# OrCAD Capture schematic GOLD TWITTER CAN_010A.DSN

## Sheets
1 PAGE1_PROPRIETARY: title: PROPRIETARY; rev: A; note: GOLD TWITTER CAN
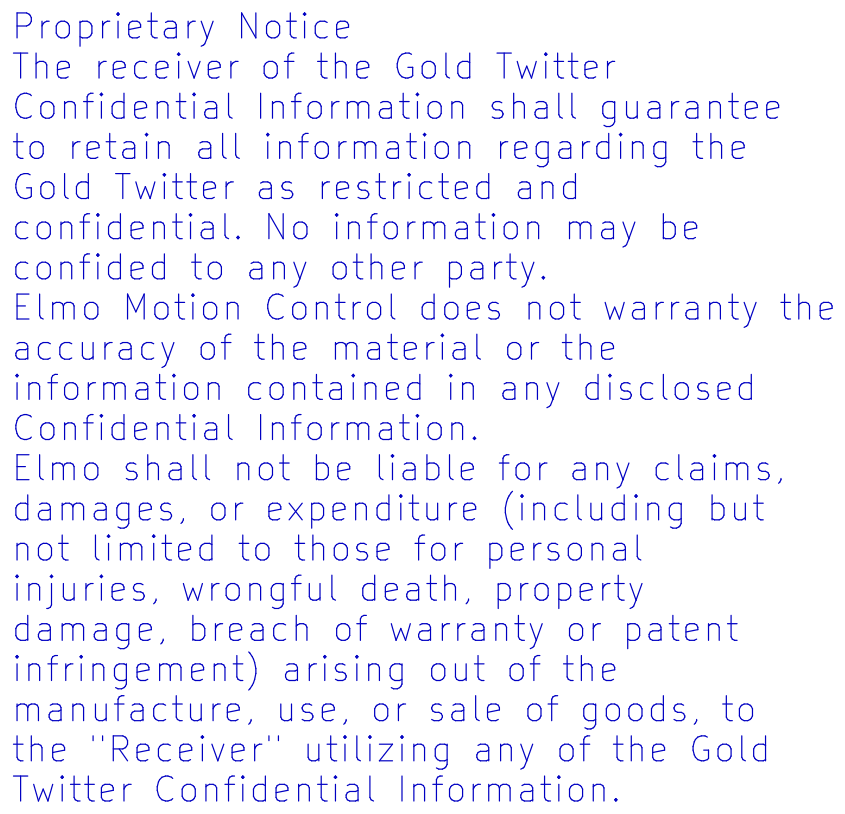
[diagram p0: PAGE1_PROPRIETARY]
2 PAGE2: size A4; title: TWI_E_B_Can_Connectors 01_200v; note: GOLD TWITTER CAN_010A.DSN
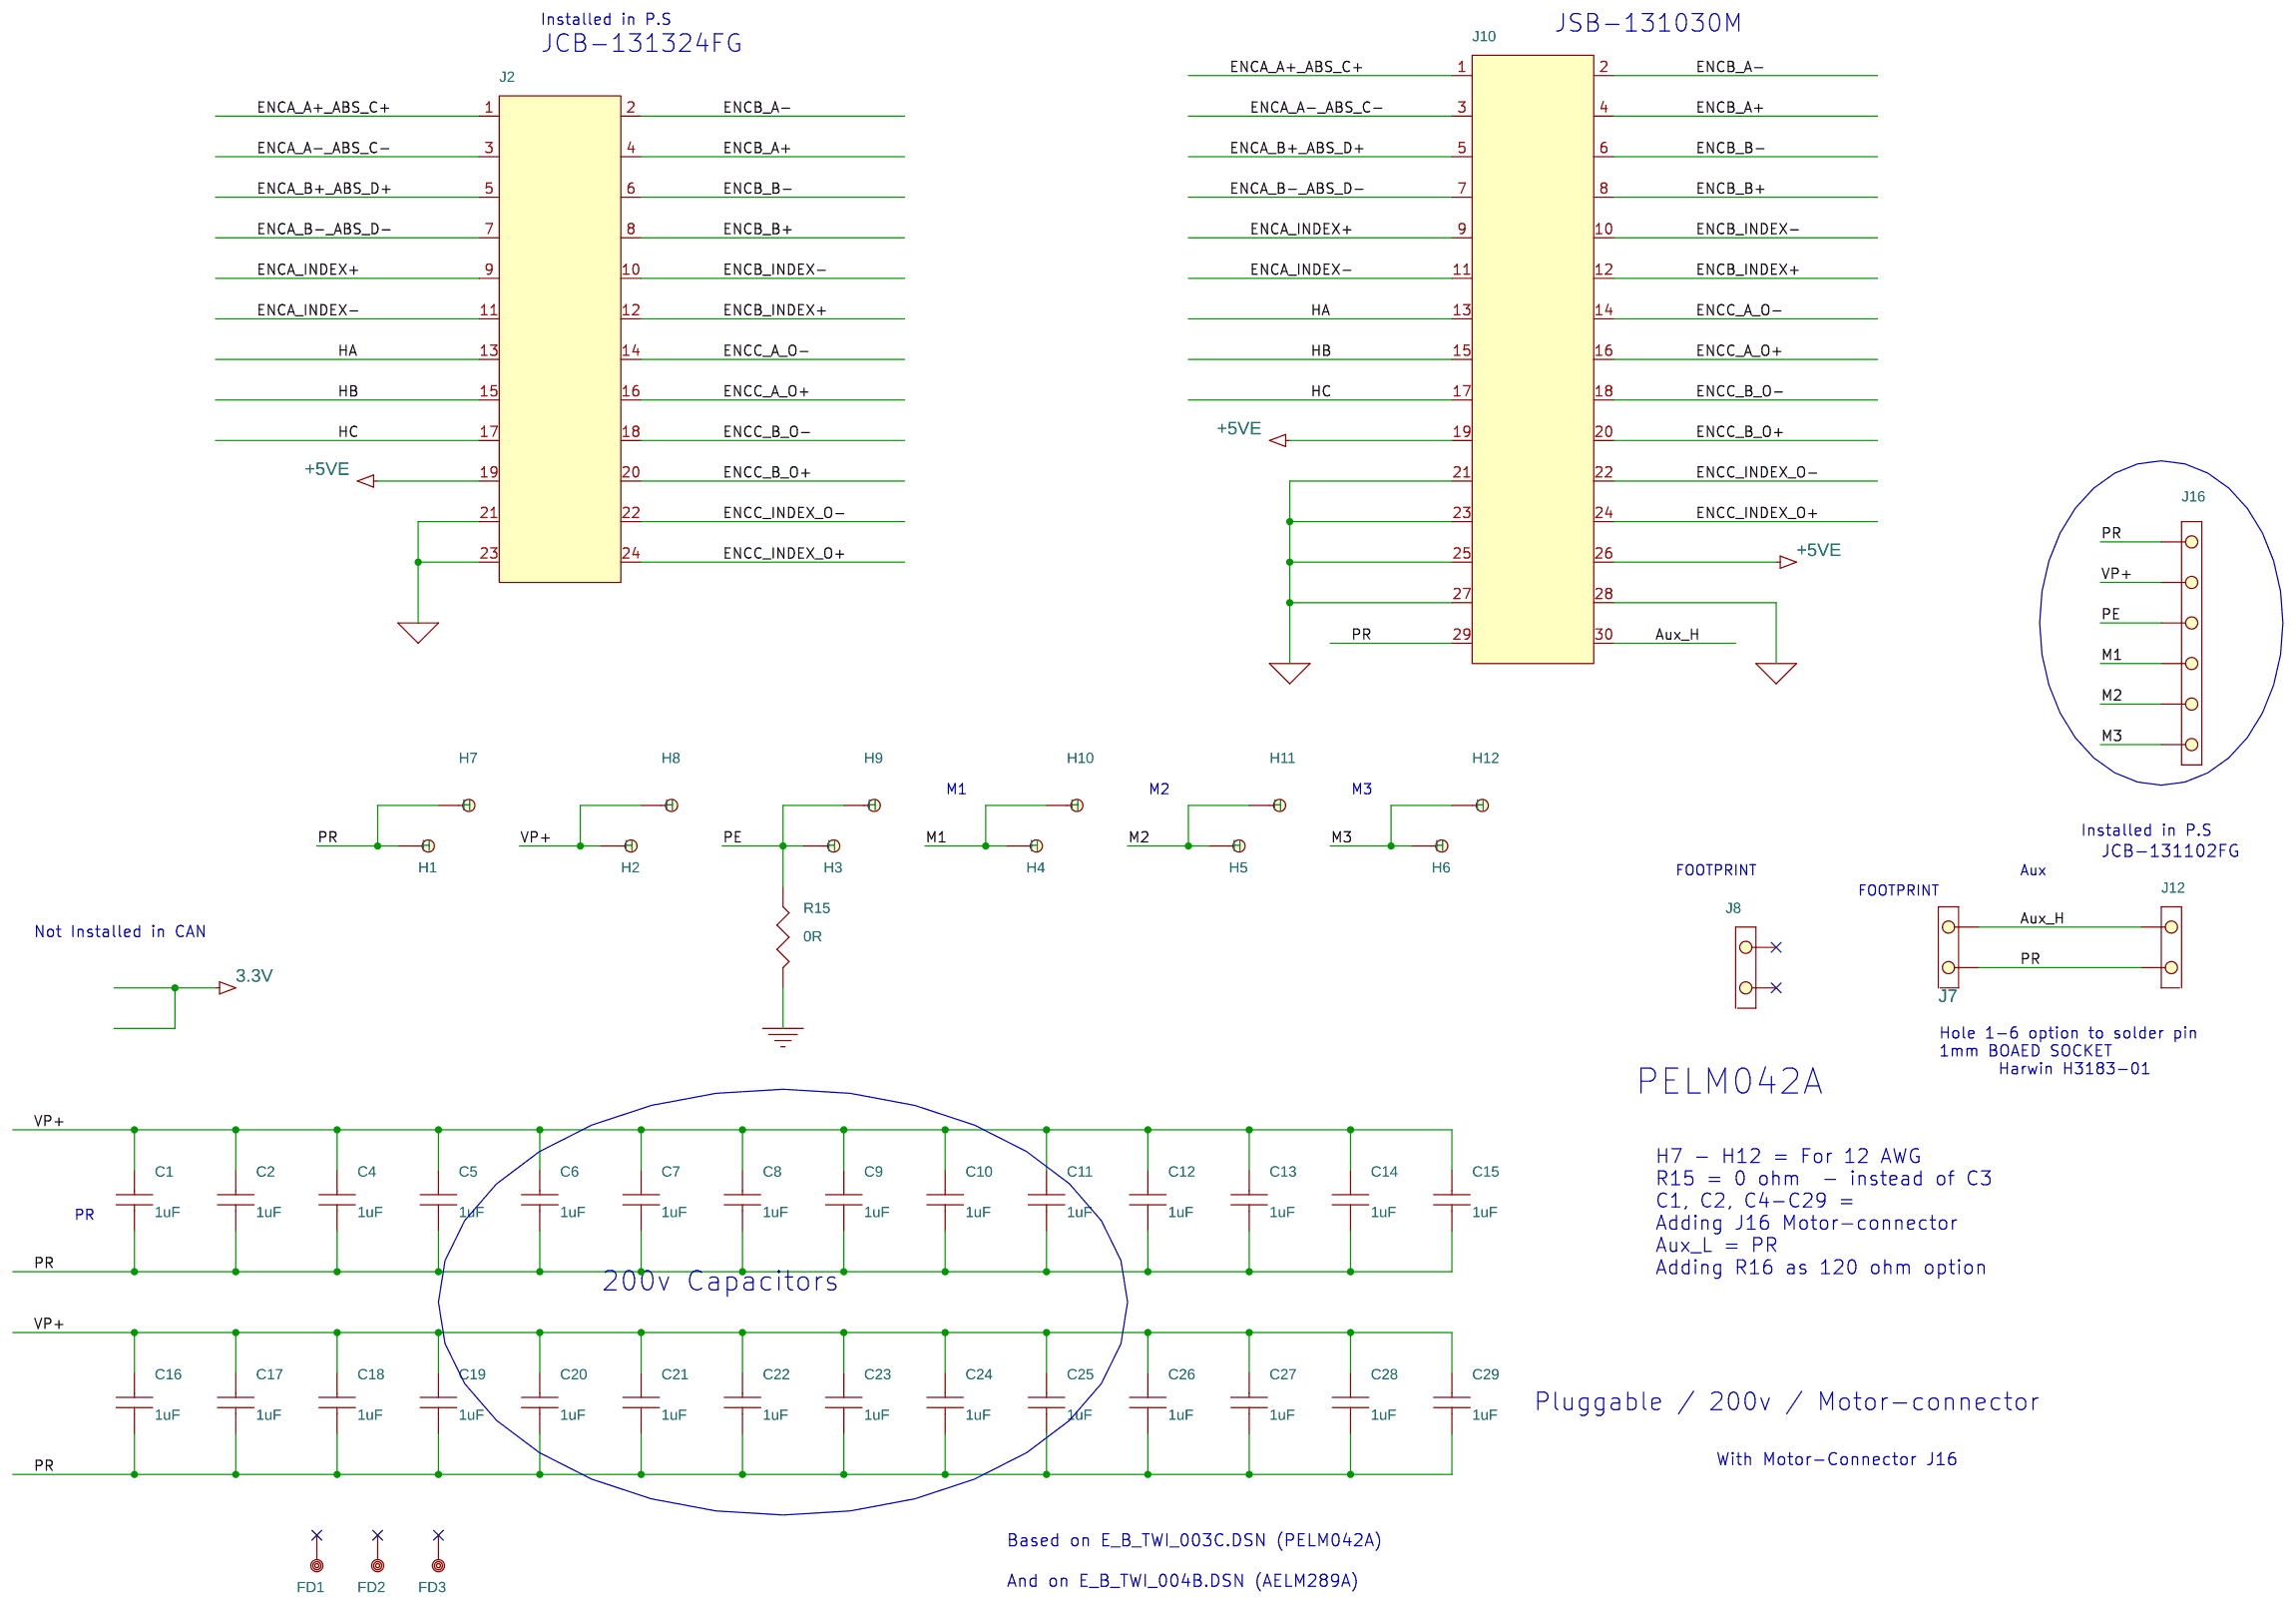
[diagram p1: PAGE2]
3 PAGE3: size A4; title: TWI_E_B_Can_Connectors 02_200v; note: GOLD TWITTER CAN_010A.DSN
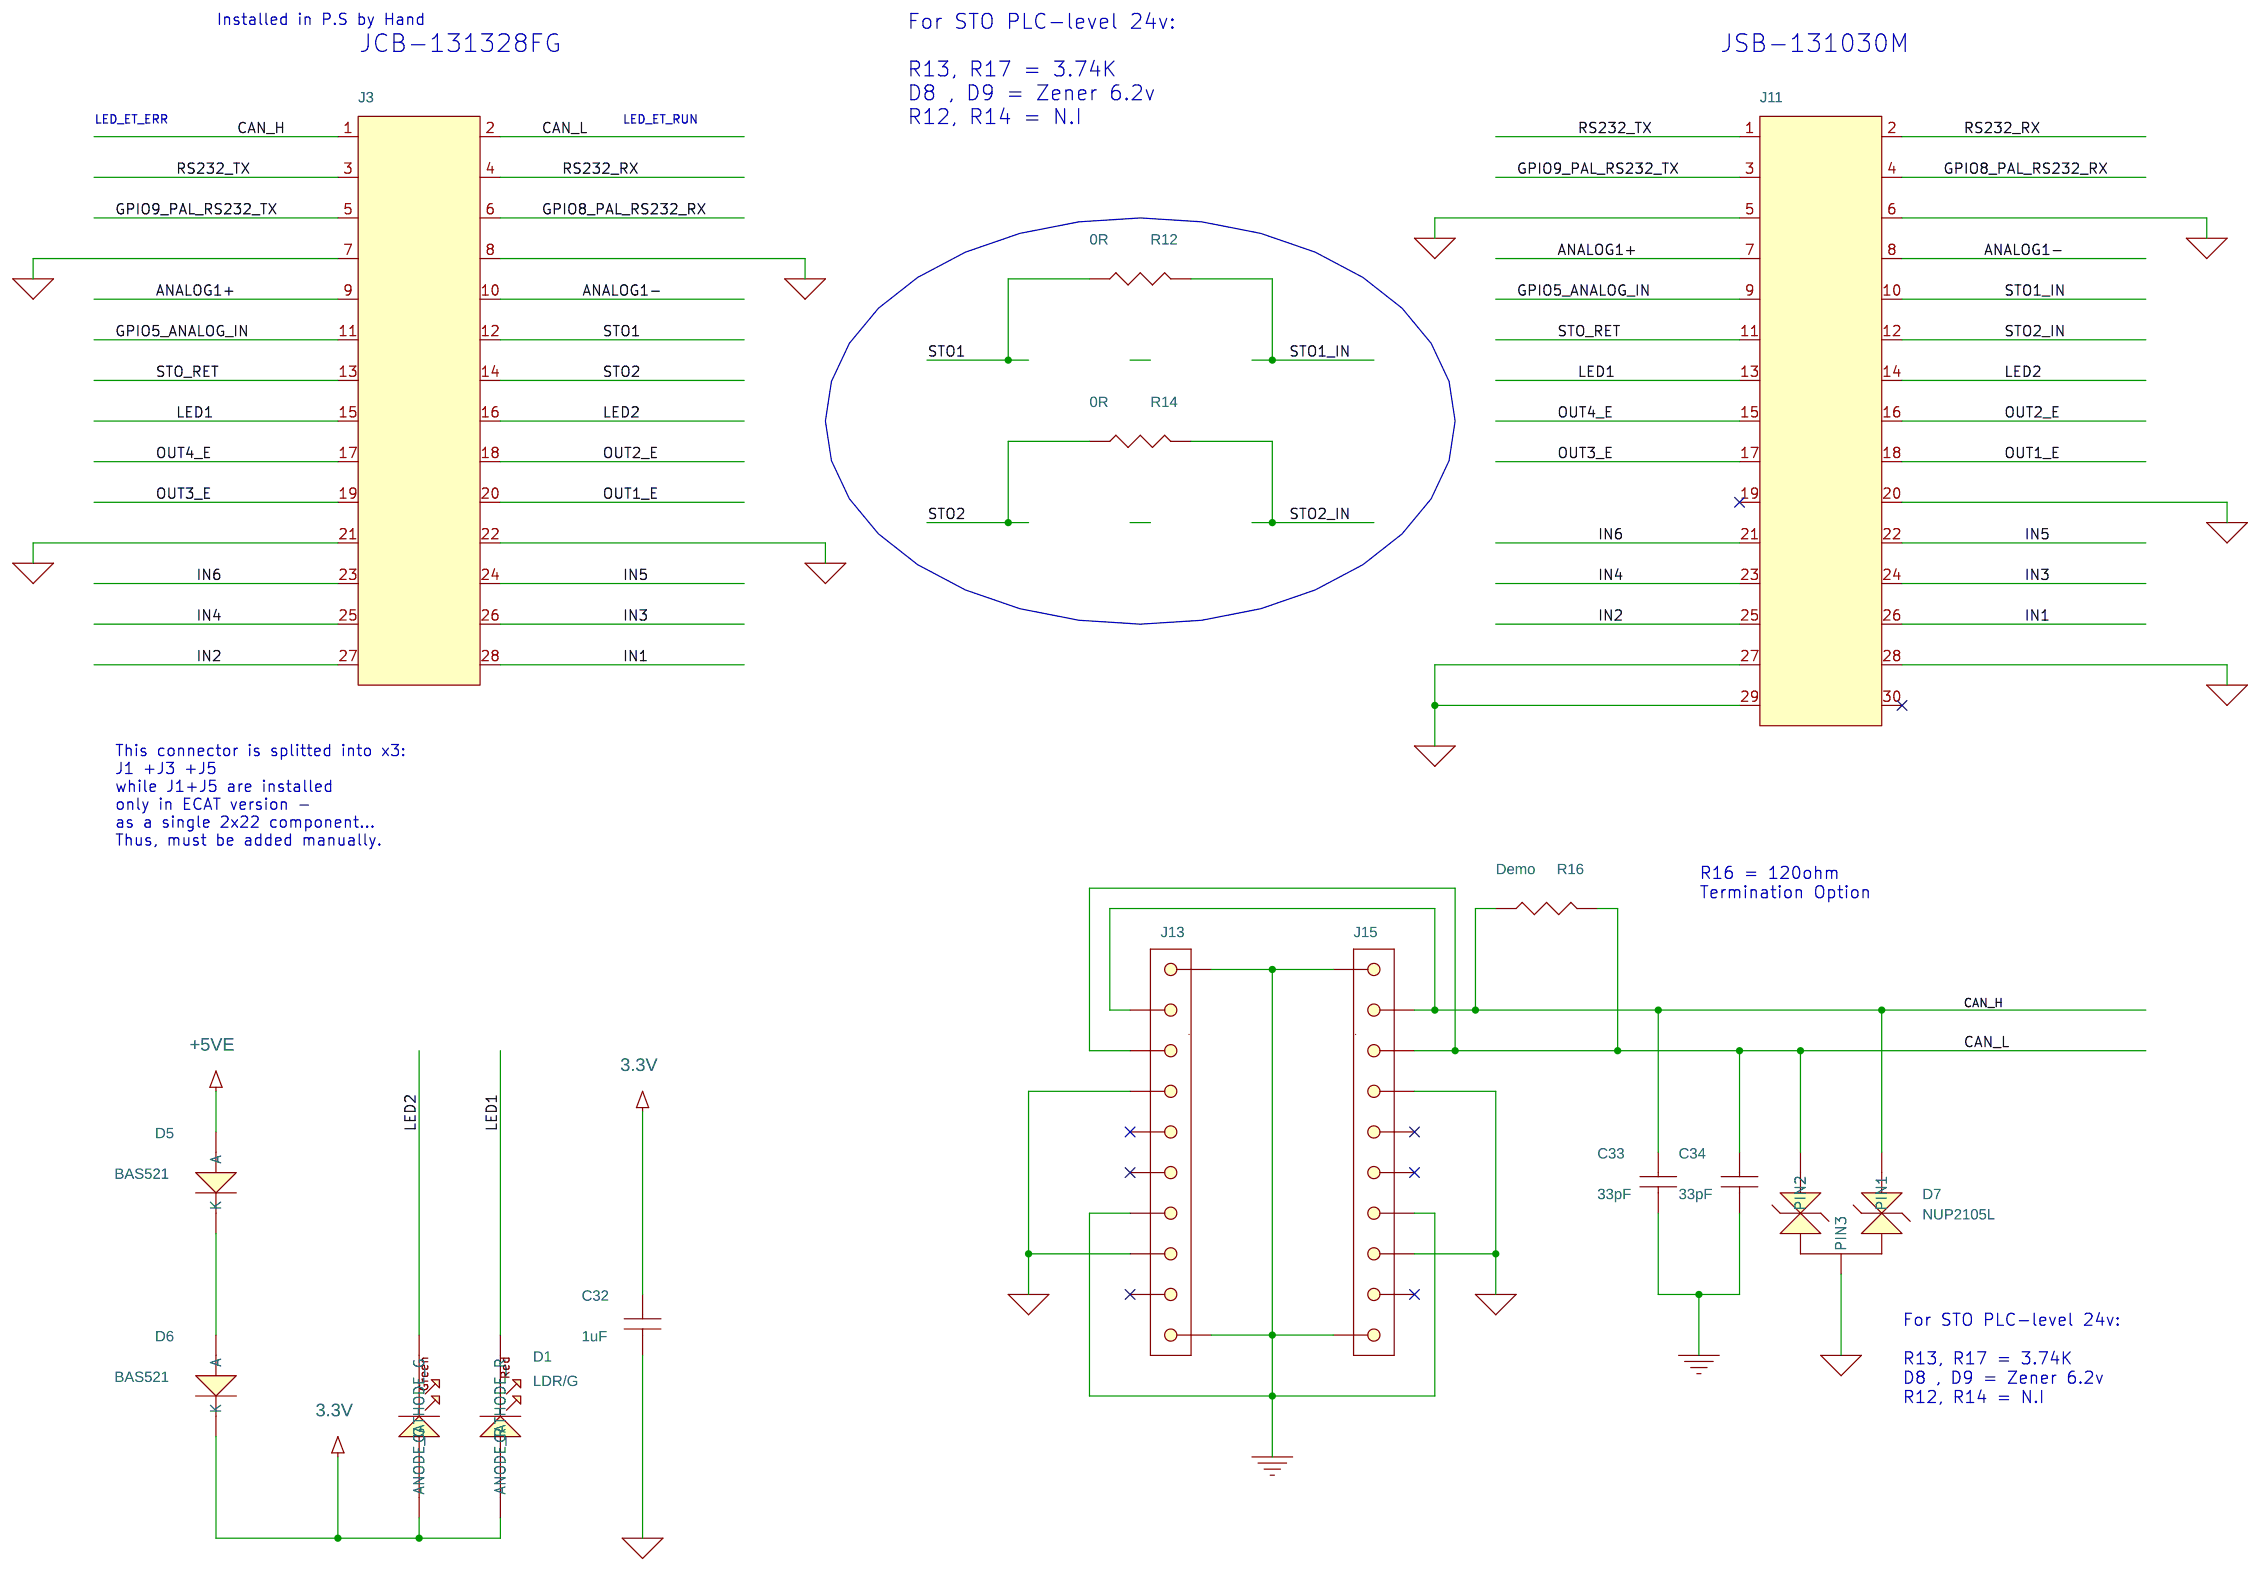
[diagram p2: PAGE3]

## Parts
sheet PAGE2
C1  1uF
C2  1uF
C4  1uF
C5  1uF
C6  1uF
C7  1uF
C8  1uF
C9  1uF
C10  1uF
C11  1uF
C12  1uF
C13  1uF
C14  1uF
C15  1uF
C16  1uF
C17  1uF
C18  1uF
C19  1uF
C20  1uF
C21  1uF
C22  1uF
C23  1uF
C24  1uF
C25  1uF
C26  1uF
C27  1uF
C28  1uF
C29  1uF
FD1  FD1
FD2  FD1
FD3  FD1
H1  H8
H2  H8
H3  H8
H4  H8
H5  H8
H6  H8
H7  H52
H8  H52
H9  H52
H10  H52
H11  H52
H12  H52
J2  J
J7  J
J8  J
J10  J
J12  J
J16  J
R15  0R
sheet PAGE3
C32  1uF
C33  33pF
C34  33pF
D1  LDR/G
D5  BAS521
D6  BAS521
D7  NUP2105L
J3  J
J11  J
J13  J
J15  J
R12  0R
R14  0R
R16  Demo

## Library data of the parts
C1 C2 C4-C29 = C1uF_200v_X7R_1206
FD1-FD3 = FIDUCIAL1_FD1
H1-H6 = HOLE08_H08
H7-H12 = HOLE52_H52
J2 = HEADER2x12PF1.27_4.3_HEADER194
J7 = HEADER52A_FP12
J8 = HEADER2P1.27mmHEADER278A
J10 J11 = HEADER2x15P1mm_HEADER283
J12 = HEADER2PF2mm_4.3mm_HEADER52
J16 = TB6P3.5mm_TB54
R15 = 0R_1206
C32 = C1uF_10v_X5R_0402
C33 C34 = C33pF_50v_NPO_0402
D1 = LED_BICOLOR_LED06
D5 D6 = BAS521HT1_SOD523
D7 = NUP2105L_SOT23
J3 = HEADER2x14PF1.27_4.3_HEADER245
J13 J15 = CON1PORT8P_CON22
R12 R14 = 0R_0402
R16 = RES0402_DEMO

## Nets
3.3V: C32.1 D1.1(ANODE_R) D1.3(ANODE_G) D6.1(K)
+5VE: D5.2(A) J2.19 J10.19 J10.26
GND: C32.2 D7.3(PIN3) J2.21 J2.23 J3.7 J3.8 J3.21 J3.22 J10.21 J10.23 J10.25 J10.27 J10.28 J11.5 J11.6 J11.20 J11.27 J11.28 J11.29 J13.3 J13.7 J15.3 J15.7
GND_POWER: C33.2 C34.2 J13.6 J13.9 J13.10 J15.6 J15.9 J15.10 R15.2
ANALOG1+: J3.9 J11.7
ANALOG1-: J3.10 J11.8
Aux_H: J7.1 J10.30 J12.1
CAN_H: C33.1 D7.1(PIN1) J3.1 J13.1 J15.1 R16.1
CAN_L: C34.1 D7.2(PIN2) J3.2 J13.2 J15.2 R16.2
ENCA_A+_ABS_C+: J2.1 J10.1
ENCA_A-_ABS_C-: J2.3 J10.3
ENCA_B+_ABS_D+: J2.5 J10.5
ENCA_B-_ABS_D-: J2.7 J10.7
ENCA_INDEX+: J2.9 J10.9
ENCA_INDEX-: J2.11 J10.11
ENCB_A+: J2.4 J10.4
ENCB_A-: J2.2 J10.2
ENCB_B+: J2.8 J10.8
ENCB_B-: J2.6 J10.6
ENCB_INDEX+: J2.12 J10.12
ENCB_INDEX-: J2.10 J10.10
ENCC_A_O+: J2.16 J10.16
ENCC_A_O-: J2.14 J10.14
ENCC_B_O+: J2.20 J10.20
ENCC_B_O-: J2.18 J10.18
ENCC_INDEX_O+: J2.24 J10.24
ENCC_INDEX_O-: J2.22 J10.22
GPIO5_ANALOG_IN: J3.11 J11.9
GPIO8_PAL_RS232_RX: J3.6 J11.4
GPIO9_PAL_RS232_TX: J3.5 J11.3
HA: J2.13 J10.13
HB: J2.15 J10.15
HC: J2.17 J10.17
IN1: J3.28 J11.26
IN2: J3.27 J11.25
IN3: J3.26 J11.24
IN4: J3.25 J11.23
IN5: J3.24 J11.22
IN6: J3.23 J11.21
LED1: D1.2(CATHODE_R) J3.15 J11.13
LED2: D1.4(CATHODE_G) J3.16 J11.14
M1: H4.1(H) H10.1(H) J16.4
M2: H5.1(H) H11.1(H) J16.5
M3: H6.1(H) H12.1(H) J16.6
OUT1_E: J3.20 J11.18
OUT2_E: J3.18 J11.16
OUT3_E: J3.19 J11.17
OUT4_E: J3.17 J11.15
PE: H3.1(H) H9.1(H) J16.3 R15.1
PR: C1.2 C2.2 C4.2 C5.2 C6.2 C7.2 C8.2 C9.2 C10.2 C11.2 C12.2 C13.2 C14.2 C15.2 C16.2 C17.2 C18.2 C19.2 C20.2 C21.2 C22.2 C23.2 C24.2 C25.2 C26.2 C27.2 C28.2 C29.2 H1.1(H) H7.1(H) J7.2 J10.29 J12.2 J16.1
RS232_RX: J3.4 J11.2
RS232_TX: J3.3 J11.1
STO1: J3.12 R12.1
STO1_IN: J11.10 R12.2
STO2: J3.14 R14.1
STO2_IN: J11.12 R14.2
STO_RET: J3.13 J11.11
VP+: C1.1 C2.1 C4.1 C5.1 C6.1 C7.1 C8.1 C9.1 C10.1 C11.1 C12.1 C13.1 C14.1 C15.1 C16.1 C17.1 C18.1 C19.1 C20.1 C21.1 C22.1 C23.1 C24.1 C25.1 C26.1 C27.1 C28.1 C29.1 H2.1(H) H8.1(H) J16.2
N14985989: D5.1(K) D6.2(A)

Not connected (* = marked no-connect by the designer): FD1 1*; FD2 1*; FD3 1*; J8 1* 2*; J11 19* 30*; J13 4* 5* 8*; J15 4* 5* 8*

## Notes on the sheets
sheet 1
- Proprietary Notice
  The receiver of the Gold Twitter
  Confidential Information shall guarantee
  to retain all information regarding the
  Gold Twitter as restricted and
  confidential. No information may be
  confided to any other party.
  Elmo Motion Control does not warranty the
  accuracy of the material or the
  information contained in any disclosed
  Confidential Information.
  Elmo shall not be liable for any claims,
  damages, or expenditure (including but
  not limited to those for personal
  injuries, wrongful death, property
  damage, breach of warranty or patent
  infringement) arising out of the
  manufacture, use, or sale of goods, to
  the "Receiver" utilizing any of the Gold
  Twitter Confidential Information.
sheet 2
- Installed in P.S
- JSB-131030M
- JCB-131324FG
- M1
- M2
- M3
- Installed in P.S
- JCB-131102FG
- FOOTPRINT
- FOOTPRINT
- Aux
- Not Installed in CAN
- Hole 1-6 option to solder pin
  1mm BOAED SOCKET
         Harwin H3183-01
- PELM042A
- H7 - H12 = For 12 AWG
  R15 = 0 ohm  - instead of C3
  C1, C2, C4-C29 =
  Adding J16 Motor-connector
  Aux_L = PR
  Adding R16 as 120 ohm option
- PR
- 200v Capacitors
- Pluggable / 200v / Motor-connector
- With Motor-Connector J16
- Based on E_B_TWI_003C.DSN (PELM042A)
- And on E_B_TWI_004B.DSN (AELM289A)
sheet 3
- Installed in P.S by Hand
- For STO PLC-level 24v:
  R13, R17 = 3.74K
  D8 , D9 = Zener 6.2v
  R12, R14 = N.I
- JCB-131328FG
- JSB-131030M
- LED_ET_ERR
- LED_ET_RUN
- This connector is splitted into x3:
  J1 +J3 +J5
  while J1+J5 are installed
  only in ECAT version -
  as a single 2x22 component...
  Thus, must be added manually.
- R16 = 120ohm
  Termination Option
- For STO PLC-level 24v:
  R13, R17 = 3.74K
  D8 , D9 = Zener 6.2v
  R12, R14 = N.I
